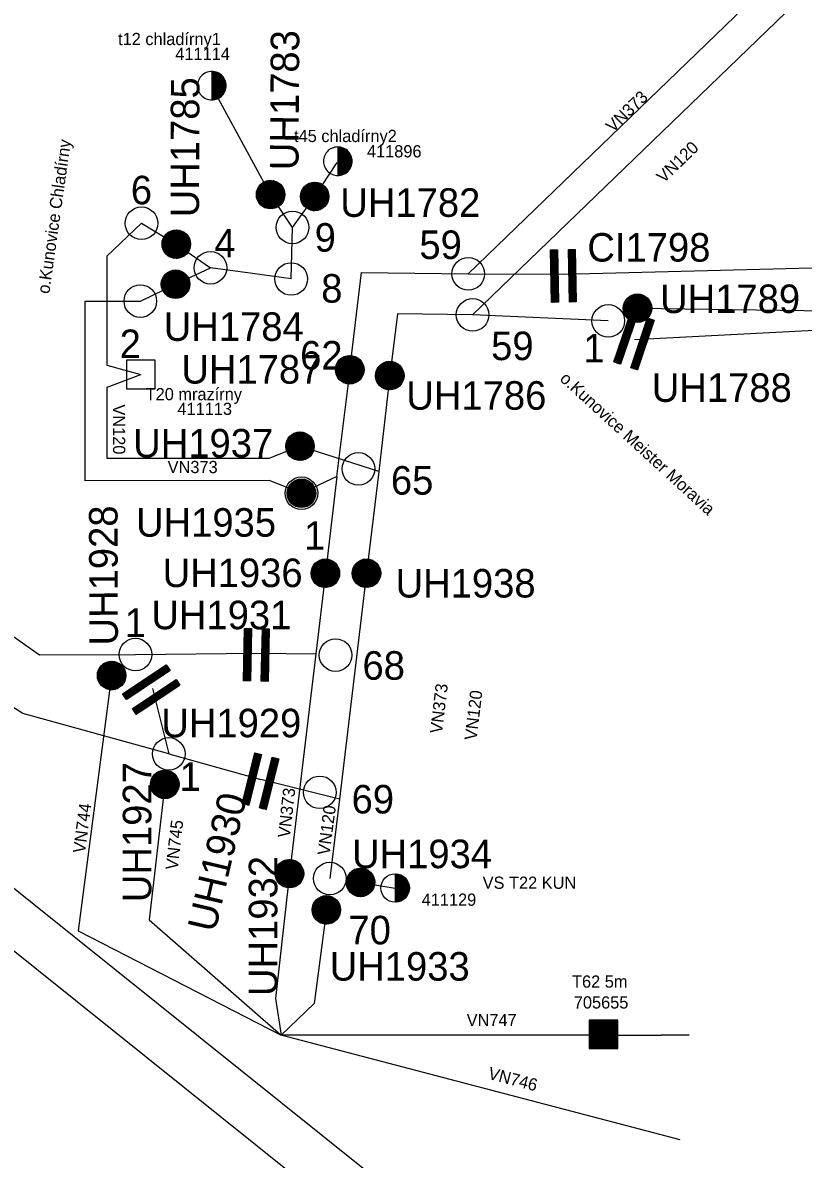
# Model space of a CAD drawing. Extents: x -541654 to -535721, y -1185255 to -1179094.
# Drawn here: x -540417 to -539460, y -1184265 to -1182871 of the extents above; entities that cross this region are included whole.
import ezdxf

# ---------------------------------------------------------------- set-up
doc = ezdxf.new("R2010")
doc.units = 0
for name, color, linetype in [('Default', 7, 'Continuous'), ('Vrstva 1', 7, 'Continuous'), ('Vrstva 2', 7, 'Continuous'), ('Vrstva 20', 7, 'Continuous'), ('Vrstva 3', 7, 'Continuous'), ('Vrstva 5', 7, 'Continuous')]:
    doc.layers.add(name, color=color, linetype=linetype)

# ---------------------------------------------------------------- blocks, each defined once
blk = doc.blocks.new('PS100')
at = {"layer": 'Default'}
for p, q in [((-17.5, -0.7), (0.7, 17.5)), ((-17.5, 0.7), (-0.7, 17.5)), ((-17.4, -2), (2, 17.4)), ((-17.3, 2.2), (-2.2, 17.3)), ((-17.2, -3.3), (3.3, 17.2)), ((-17, 4), (-4, 17)), ((-16.9, -4.4), (4.4, 16.9)), ((-16.6, -5.5), (5.5, 16.6)), ((-16.4, 6), (-6, 16.4)), ((-16.2, -6.5), (6.5, 16.2)), ((-15.8, -7.5), (7.5, 15.8)), ((-15.3, -8.4), (8.4, 15.3)), ((-15.2, 8.6), (-8.6, 15.2)), ((-14.8, -9.3), (9.3, 14.8)), ((-14.2, -10.2), (10.2, 14.2)), ((-13.6, -11), (11, 13.6)), ((-13, -11.7), (11.7, 13)), ((-12.3, -12.5), (12.5, 12.3)), ((-11.5, -13.2), (13.2, 11.5)), ((-10.8, -13.8), (13.8, 10.8)), ((-9.9, -14.4), (14.4, 9.9)), ((-9.1, -14.9), (14.9, 9.1)), ((-8.2, -15.5), (15.5, 8.2)), ((-7.2, -15.9), (15.9, 7.2)), ((-6.2, -16.3), (16.3, 6.2)), ((-5.2, -16.7), (16.7, 5.2)), ((-4.1, -17), (17, 4.1)), ((-2.9, -17.2), (17.2, 2.9)), ((-1.6, -17.4), (17.4, 1.6)), ((-0.3, -17.5), (17.5, 0.3)), ((1.1, -17.4), (17.4, -1.1)), ((2.7, -17.3), (17.3, -2.7)), ((4.5, -16.9), (16.9, -4.5)), ((6.7, -16.2), (16.2, -6.7)), ((9.7, -14.5), (14.5, -9.7))]:
    blk.add_line(p, q, dxfattribs=at)
blk.add_circle((0, 0), 17.5, dxfattribs=at)
blk = doc.blocks.new('PS140')
at = {"layer": 'Default'}
for p, q in [((-17.5, 0), (0, 17.5)), ((-17.4, -1.4), (1.4, 17.4)), ((-17.4, 1.5), (-1.5, 17.4)), ((-17.3, -2.6), (2.6, 17.3)), ((-17.2, 3.1), (-3.1, 17.2)), ((-17.1, -3.8), (3.8, 17.1)), ((-16.8, -4.9), (4.9, 16.8)), ((-16.8, 5), (-5, 16.8)), ((-16.4, -6), (6, 16.4)), ((-16, -7), (7, 16)), ((-15.9, 7.2), (-7.2, 15.9)), ((-15.6, -8), (8, 15.6)), ((-15.1, -8.9), (8.9, 15.1)), ((-14.5, -9.8), (9.8, 14.5)), ((-13.9, -10.6), (10.6, 13.9)), ((-13.8, 10.8), (-10.8, 13.8)), ((-13.3, -11.4), (11.4, 13.3)), ((-12.6, -12.1), (12.1, 12.6)), ((-11.9, -12.8), (12.8, 11.9)), ((-11.2, -13.5), (13.5, 11.2)), ((-10.4, -14.1), (14.1, 10.4)), ((-9.5, -14.7), (14.7, 9.5)), ((-8.6, -15.2), (15.2, 8.6)), ((-7.7, -15.7), (15.7, 7.7)), ((-6.7, -16.1), (16.1, 6.7)), ((-5.7, -16.5), (16.5, 5.7)), ((-4.6, -16.9), (16.9, 4.6)), ((-3.5, -17.1), (17.1, 3.5)), ((-2.3, -17.3), (17.3, 2.3)), ((-1, -17.5), (17.5, 1)), ((0.4, -17.5), (17.5, -0.4)), ((1.9, -17.4), (17.4, -1.9)), ((3.6, -17.1), (17.1, -3.6)), ((5.5, -16.6), (16.6, -5.5)), ((8, -15.6), (15.6, -8))]:
    blk.add_line(p, q, dxfattribs=at)
blk.add_circle((0, 0), 17.5, dxfattribs=at)
blk = doc.blocks.new('PS150')
at = {"layer": 'Default'}
for p, q in [((-15.1, 22.4), (-7.4, 30.1)), ((-15.1, 23.8), (-8.8, 30.1)), ((-15.1, 25.2), (-10.2, 30.1)), ((-15.1, 26.6), (-11.6, 30.1)), ((-15.1, 28), (-13, 30.1)), ((-15.1, 29.4), (-14.4, 30.1)), ((-15.1, 20.9), (-6.5, 29.5)), ((-15.1, 19.5), (-6.5, 28.1)), ((6.7, 22.6), (14.1, 30.1)), ((6.7, 24), (12.7, 30.1)), ((6.7, 25.4), (11.3, 30.1)), ((6.7, 26.8), (9.9, 30.1)), ((6.7, 28.3), (8.5, 30.1)), ((6.7, 29.7), (7, 30.1)), ((6.7, 21.2), (15.2, 29.8)), ((6.7, 19.8), (15.2, 28.3)), ((-15.1, 18.1), (-6.5, 26.7)), ((-15.1, 16.7), (-6.5, 25.3)), ((-15.1, 15.3), (-6.5, 23.9)), ((-15.1, 13.9), (-6.5, 22.4)), ((-15.1, 12.5), (-6.5, 21)), ((-15.1, 11), (-6.5, 19.6)), ((-15.1, 9.6), (-6.5, 18.2)), ((-15.1, 8.2), (-6.5, 16.8)), ((-15.1, 6.8), (-6.5, 15.4)), ((-15.1, 5.4), (-6.5, 14)), ((6.7, 18.4), (15.2, 26.9)), ((6.7, 16.9), (15.2, 25.5)), ((6.7, 15.5), (15.2, 24.1)), ((6.7, 14.1), (15.2, 22.7)), ((6.7, 12.7), (15.2, 21.3)), ((6.7, 11.3), (15.2, 19.9)), ((6.7, 9.9), (15.2, 18.4)), ((6.7, 8.5), (15.2, 17)), ((6.7, 7.1), (15.2, 15.6)), ((6.7, 5.6), (15.2, 14.2)), ((-15.1, 4), (-6.5, 12.5)), ((-15.1, 2.6), (-6.5, 11.1)), ((-15.1, 1.2), (-6.5, 9.7)), ((-15.1, -0.3), (-6.5, 8.3)), ((-15.1, -1.7), (-6.5, 6.9)), ((-15.1, -3.1), (-6.5, 5.5)), ((-15.1, -4.5), (-6.5, 4.1)), ((-15.1, -5.9), (-6.5, 2.6)), ((-15.1, -7.3), (-6.5, 1.2)), ((6.7, 4.2), (15.2, 12.8)), ((6.7, 2.8), (15.2, 11.4)), ((6.7, 1.4), (15.2, 10)), ((6.7, 0), (15.2, 8.5)), ((6.7, -1.4), (15.2, 7.1)), ((6.7, -2.8), (15.2, 5.7)), ((6.7, -4.3), (15.2, 4.3)), ((6.7, -5.7), (15.2, 2.9)), ((6.7, -7.1), (15.2, 1.5)), ((6.7, -8.5), (15.2, 0.1)), ((-15.1, -8.7), (-6.5, -0.2)), ((-15.1, -10.2), (-6.5, -1.6)), ((-15.1, -11.6), (-6.5, -3)), ((-15.1, -13), (-6.5, -4.4)), ((-15.1, -14.4), (-6.5, -5.8)), ((-15.1, -15.8), (-6.5, -7.3)), ((-15.1, -17.2), (-6.5, -8.7)), ((-15.1, -18.6), (-6.5, -10.1)), ((-15.1, -20.1), (-6.5, -11.5)), ((-15.1, -21.5), (-6.5, -12.9)), ((6.7, -9.9), (15.2, -1.4)), ((6.7, -11.3), (15.2, -2.8)), ((6.7, -12.7), (15.2, -4.2)), ((6.7, -14.2), (15.2, -5.6)), ((6.7, -15.6), (15.2, -7)), ((6.7, -17), (15.2, -8.4)), ((6.7, -18.4), (15.2, -9.8)), ((6.7, -19.8), (15.2, -11.3)), ((6.7, -21.2), (15.2, -12.7)), ((-15.1, -22.9), (-6.5, -14.3)), ((-15.1, -24.3), (-6.5, -15.7)), ((-15.1, -25.7), (-6.5, -17.2)), ((-15.1, -27.1), (-6.5, -18.6)), ((-15.1, -28.5), (-6.5, -20)), ((-15.1, -30), (-6.5, -21.4)), ((-15.1, -31.4), (-6.5, -22.8)), ((-15.1, -32.8), (-6.5, -24.2)), ((-15, -34.2), (-6.5, -25.6)), ((-13.6, -34.2), (-6.5, -27.1)), ((6.7, -22.6), (15.2, -14.1)), ((6.7, -24.1), (15.2, -15.5)), ((6.7, -25.5), (15.2, -16.9)), ((6.7, -26.9), (15.2, -18.3)), ((6.7, -28.3), (15.2, -19.7)), ((6.7, -29.7), (15.2, -21.2)), ((6.7, -31.1), (15.2, -22.6)), ((6.7, -32.5), (15.2, -24)), ((6.7, -34), (15.2, -25.4)), ((7.9, -34.2), (15.2, -26.8)), ((-12.2, -34.2), (-6.5, -28.5)), ((-10.8, -34.2), (-6.5, -29.9)), ((-9.4, -34.2), (-6.5, -31.3)), ((-8, -34.2), (-6.5, -32.7)), ((-6.5, -34.2), (-6.5, -34.1)), ((9.3, -34.2), (15.2, -28.2)), ((10.7, -34.2), (15.2, -29.6)), ((12.1, -34.2), (15.2, -31)), ((13.5, -34.2), (15.2, -32.5)), ((14.9, -34.2), (15.2, -33.9))]:
    blk.add_line(p, q, dxfattribs=at)
for points in [[(-6.5, 30.1), (-6.5, -34.2), (-15.1, -34.2), (-15.1, 30.1)], [(15.2, 30.1), (15.2, -34.2), (6.7, -34.2), (6.7, 30.1)]]:
    blk.add_lwpolyline(points, close=True, dxfattribs=at)
blk = doc.blocks.new('PS610')
at = {"layer": 'Default'}
for p, q in [((0, 16.2), (1.3, 17.4)), ((0, 14.7), (2.5, 17.3)), ((0, 13.3), (3.7, 17.1)), ((0, 11.9), (4.9, 16.8)), ((0, 10.5), (5.9, 16.4)), ((0, 9.1), (7, 16)), ((0, 7.7), (7.9, 15.6)), ((0, 6.3), (8.8, 15.1)), ((0, 4.8), (9.7, 14.5)), ((0, 3.4), (10.5, 14)), ((0, 2), (11.3, 13.3)), ((0, 0.6), (12, 12.7)), ((0, -0.8), (12.8, 12)), ((0, -2.2), (13.4, 11.2)), ((0, -3.6), (14, 10.4)), ((0, -5), (14.6, 9.6)), ((0, -6.5), (15.2, 8.7)), ((0, -7.9), (15.6, 7.8)), ((0, -9.3), (16.1, 6.8)), ((0, -10.7), (16.5, 5.8)), ((0, -12.1), (16.8, 4.7)), ((0, -13.5), (17.1, 3.6)), ((0, -14.9), (17.3, 2.4)), ((0, -16.4), (17.4, 1.1)), ((0.3, -17.5), (17.5, -0.3)), ((1.8, -17.4), (17.4, -1.8)), ((3.5, -17.1), (17.1, -3.5)), ((5.4, -16.7), (16.7, -5.4)), ((7.8, -15.7), (15.6, -7.8))]:
    blk.add_line(p, q, dxfattribs=at)
blk.add_lwpolyline([(0, 17.5), (0, -17.5)], dxfattribs=at)
blk.add_circle((0, 0), 17.5, dxfattribs=at)
blk = doc.blocks.new('PS800')
at = {"layer": 'Vrstva 2'}
blk.add_circle((0, 0), 20, dxfattribs=at)
blk = doc.blocks.new('PS650')
at = {"layer": 'Vrstva 20'}
for points in [[(17.5, 17.5), (-17.5, 17.5)], [(-17.5, 17.5), (-17.5, -17.5)], [(17.5, -17.5), (17.5, 17.5)], [(-17.5, -17.5), (17.5, -17.5)]]:
    blk.add_lwpolyline(points, dxfattribs=at)
blk = doc.blocks.new('PS630')
at = {"layer": 'Default'}
for p, q in [((-16.6, -14.9), (17.1, 18.7)), ((-16.6, -13.5), (15.7, 18.7)), ((-16.6, -12.1), (14.2, 18.7)), ((-16.6, -10.7), (12.8, 18.7)), ((-16.6, -9.3), (11.4, 18.7)), ((-16.6, -7.9), (10, 18.7)), ((-16.6, -6.5), (8.6, 18.7)), ((-16.6, -5), (7.2, 18.7)), ((-16.6, -3.6), (5.8, 18.7)), ((-16.6, -2.2), (4.3, 18.7)), ((-16.6, -0.8), (2.9, 18.7)), ((-16.6, 0.6), (1.5, 18.7)), ((-16.6, 2), (0.1, 18.7)), ((-16.6, 3.4), (-1.3, 18.7)), ((-16.6, 4.9), (-2.7, 18.7)), ((-16.6, 6.3), (-4.1, 18.7)), ((-16.6, 7.7), (-5.6, 18.7)), ((-16.6, 9.1), (-7, 18.7)), ((-16.6, 10.5), (-8.4, 18.7)), ((-16.6, 11.9), (-9.8, 18.7)), ((-16.6, 13.3), (-11.2, 18.7)), ((-16.6, 14.8), (-12.6, 18.7)), ((-16.6, 16.2), (-14, 18.7)), ((-16.6, 17.6), (-15.5, 18.7)), ((-16.5, -16.3), (18.4, 18.6)), ((-15.1, -16.3), (18.4, 17.2)), ((-13.7, -16.3), (18.4, 15.8)), ((-12.3, -16.3), (18.4, 14.4)), ((-10.9, -16.3), (18.4, 13)), ((-9.4, -16.3), (18.4, 11.6)), ((-8, -16.3), (18.4, 10.2)), ((-6.6, -16.3), (18.4, 8.7)), ((-5.2, -16.3), (18.4, 7.3)), ((-3.8, -16.3), (18.4, 5.9)), ((-2.4, -16.3), (18.4, 4.5)), ((-1, -16.3), (18.4, 3.1)), ((0.5, -16.3), (18.4, 1.7)), ((1.9, -16.3), (18.4, 0.3)), ((3.3, -16.3), (18.4, -1.2)), ((4.7, -16.3), (18.4, -2.6)), ((6.1, -16.3), (18.4, -4)), ((7.5, -16.3), (18.4, -5.4)), ((8.9, -16.3), (18.4, -6.8)), ((10.4, -16.3), (18.4, -8.2)), ((11.8, -16.3), (18.4, -9.6)), ((13.2, -16.3), (18.4, -11.1)), ((14.6, -16.3), (18.4, -12.5)), ((16, -16.3), (18.4, -13.9)), ((17.4, -16.3), (18.4, -15.3))]:
    blk.add_line(p, q, dxfattribs=at)
for points in [[(-16.6, 18.7), (-16.6, -16.3)], [(18.4, 18.7), (-16.6, 18.7)], [(-16.6, 18.7), (-16.6, -16.3)], [(18.4, -16.3), (18.4, 18.7)], [(-16.6, -16.3), (18.4, -16.3)]]:
    blk.add_lwpolyline(points, dxfattribs=at)
blk = doc.blocks.new('PS611')
at = {"layer": 'Default'}
for p, q in [((0, 16.2), (1.3, 17.4)), ((0, 14.7), (2.5, 17.3)), ((0, 13.3), (3.7, 17.1)), ((0, 11.9), (4.9, 16.8)), ((0, 10.5), (5.9, 16.4)), ((0, 9.1), (7, 16)), ((0, 7.7), (7.9, 15.6)), ((0, 6.3), (8.8, 15.1)), ((0, 4.8), (9.7, 14.5)), ((0, 3.4), (10.5, 14)), ((0, 2), (11.3, 13.3)), ((0, 0.6), (12, 12.7)), ((0, -0.8), (12.8, 12)), ((0, -2.2), (13.4, 11.2)), ((0, -3.6), (14, 10.4)), ((0, -5), (14.6, 9.6)), ((0, -6.5), (15.2, 8.7)), ((0, -7.9), (15.6, 7.8)), ((0, -9.3), (16.1, 6.8)), ((0, -10.7), (16.5, 5.8)), ((0, -12.1), (16.8, 4.7)), ((0, -13.5), (17.1, 3.6)), ((0, -14.9), (17.3, 2.4)), ((0, -16.4), (17.4, 1.1)), ((0.3, -17.5), (17.5, -0.3)), ((1.8, -17.4), (17.4, -1.8)), ((3.5, -17.1), (17.1, -3.5)), ((5.4, -16.7), (16.7, -5.4)), ((7.8, -15.7), (15.6, -7.8))]:
    blk.add_line(p, q, dxfattribs=at)
for points in [[(17.5, 0), (17.4, 1.8), (17.1, 3.6), (16.6, 5.4), (16, 7.1), (15.2, 8.8), (14.2, 10.3), (13, 11.7), (11.7, 13), (10.3, 14.2), (8.7, 15.2), (7.1, 16), (5.4, 16.6), (3.6, 17.1), (1.8, 17.4), (0, 17.5), (-1.8, 17.4), (-3.6, 17.1), (-5.4, 16.6), (-7.1, 16), (-8.8, 15.2), (-10.3, 14.2), (-11.7, 13), (-13, 11.7), (-14.2, 10.3), (-15.2, 8.7), (-16, 7.1), (-16.6, 5.4), (-17.1, 3.6), (-17.4, 1.8), (-17.5, 0), (-17.4, -1.8), (-17.1, -3.6), (-16.6, -5.4), (-16, -7.1), (-15.2, -8.8), (-14.2, -10.3), (-13, -11.7), (-11.7, -13), (-10.3, -14.2), (-8.8, -15.2), (-7.1, -16), (-5.4, -16.6), (-3.6, -17.1), (-1.8, -17.4), (0, -17.5), (1.8, -17.4), (3.6, -17.1), (5.4, -16.6), (7.1, -16), (8.8, -15.2), (10.3, -14.2), (11.7, -13), (13, -11.7), (14.2, -10.3), (15.2, -8.8), (16, -7.1), (16.6, -5.4), (17.1, -3.6), (17.4, -1.8), (17.5, 0)], [(0, 17.5), (0, -17.5)]]:
    blk.add_lwpolyline(points, dxfattribs=at)

msp = doc.modelspace()

# ---------------------------------------------------------------- linework, layer by layer
at = {"layer": 'Default'}
for points in [[(-535721.4, -1181322.7), (-538502.4, -1179093.8), (-541654.5, -1183026.4), (-538873.5, -1185255.4)], [(-535805.8, -1181332), (-538493.1, -1179178.1), (-541570.1, -1183017.1), (-538882.8, -1185171.1)]]:
    msp.add_lwpolyline(points, close=True, dxfattribs=at)
at = {"layer": 'Vrstva 1'}
for points in [[(-538730.2, -1181781.1), (-538745.8, -1181888.8), (-538896.2, -1182293.4), (-539271.4, -1182655.8), (-539865.4, -1183229.4)], [(-539870.7, -1183179.1), (-539298.4, -1182626.3)], [(-540113.1, -1183082), (-540184.9, -1182950.2)], [(-540059.1, -1183084.2), (-540031.4, -1183042.7)], [(-540086.3, -1183122.1), (-540113.1, -1183082)], [(-540086.3, -1183122.1), (-540059.1, -1183084.2)], [(-540313.8, -1183157.6), (-540271.5, -1183117.1)], [(-540271.5, -1183117.1), (-540228.8, -1183142.7)], [(-540087.9, -1183185.4), (-540086.3, -1183122.1)], [(-540228.8, -1183142.7), (-540186.9, -1183171.6)], [(-540313.8, -1183157.6), (-540313.8, -1183291.1), (-540272.4, -1183302.6)], [(-540229.7, -1183191.8), (-540186.9, -1183171.6)], [(-540135.2, -1183178.8), (-540186.9, -1183171.6)], [(-539754.1, -1183179.6), (-539433, -1183171.4), (-539338.5, -1183192.6)], [(-540087.9, -1183185.4), (-540135.2, -1183178.8)], [(-540016.1, -1183296.7), (-540001.7, -1183177.6), (-539870.7, -1183179.1)], [(-539870.7, -1183179.1), (-539754.1, -1183179.6)], [(-540272.9, -1183212.5), (-540229.7, -1183191.8)], [(-540075.3, -1183448.2), (-540115.1, -1183432.6), (-540340.7, -1183432.8), (-540340.6, -1183212.5), (-540272.9, -1183212.5)], [(-539865.4, -1183229.4), (-539957.4, -1183228.3), (-539967, -1183303.9)], [(-539699, -1183236.8), (-539865.4, -1183229.4), (-539865.4, -1183229.4)], [(-539663.2, -1183221.2), (-539429.6, -1183224.5), (-539429.6, -1183393.8), (-539292.9, -1183393.8)], [(-539666.8, -1183259.6), (-539335.9, -1183242.5)], [(-540016.1, -1183296.7), (-540032.2, -1183427.6)], [(-540077.1, -1183390.5), (-540115.2, -1183405.7), (-540313.4, -1183405.6), (-540313.4, -1183318), (-540272.4, -1183302.6)], [(-539967, -1183303.9), (-539980.5, -1183421.3)], [(-539980.5, -1183421.3), (-540077.1, -1183390.5)], [(-539980.5, -1183421.3), (-539995.6, -1183546.3)], [(-540032.1, -1183427.6), (-540075.3, -1183448.2)], [(-540032.1, -1183427.6), (-540046, -1183546.3)], [(-540046, -1183546.3), (-540057.8, -1183644.9)], [(-539995.6, -1183546.3), (-540028.8, -1183823.3)], [(-540238, -1183767.8), (-540417.2, -1183718.4), (-540591.8, -1183607), (-541124.4, -1183583.7)], [(-540470.7, -1183594.2), (-540396.7, -1183646.3), (-540278.9, -1183646)], [(-540278.9, -1183646), (-540130.6, -1183644.3)], [(-540130.6, -1183644.3), (-540057.8, -1183644.9)], [(-540057.8, -1183644.9), (-540090, -1183914.6)], [(-540308.1, -1183671.6), (-540349.2, -1183984.9), (-540100, -1184112.8)], [(-540257.8, -1183687.7), (-540238, -1183767.8)], [(-540238, -1183767.8), (-540125.1, -1183799.2)], [(-540028.8, -1183823.3), (-540125.1, -1183799.2)], [(-540242.9, -1183805.1), (-540262.2, -1183971.2), (-540100, -1184112.8)], [(-540028.8, -1183823.3), (-540040.5, -1183920.6)], [(-540090, -1183914.6), (-540107, -1184067.6), (-540100, -1184112.8)], [(-540002.9, -1183925.4), (-539960.4, -1183932.2)], [(-540044.8, -1183959), (-540059.8, -1184073.9), (-540100, -1184112.8)], [(-539610.8, -1184241), (-540100, -1184112.8)], [(-539724.5, -1184112.8), (-540100, -1184112.8)], [(-539705.8, -1184112.8), (-539724.5, -1184112.8)], [(-539705.8, -1184112.8), (-539634.1, -1184112.6)], [(-539600, -1184112.8), (-539634.1, -1184112.6)]]:
    msp.add_lwpolyline(points, dxfattribs=at)

# ---------------------------------------------------------------- block references
at = {"layer": 'Vrstva 2'}
for name, p, rotation in [('PS140', (-540113.1, -1183082), 107.19590279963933), ('PS140', (-540059.1, -1183084.2), -66.5734055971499), ('PS140', (-540228.8, -1183142.7), -28.299599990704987), ('PS150', (-539754.1, -1183179.6), 1.0974722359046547), ('PS140', (-540229.7, -1183191.8), -137.72051106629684), ('PS140', (-539663.2, -1183221.2), 43.89927496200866), ('PS150', (-539666.8, -1183259.6), -18.630803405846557), ('PS140', (-540016.1, -1183296.7), 84.6160527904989), ('PS140', (-539967, -1183303.9), 81.48321110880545), ('PS140', (-540077.1, -1183390.5), 7.688058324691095), ('PS140', (-540075.3, -1183448.2), 59.104705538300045), ('PS140', (-540046, -1183546.3), 82.97227774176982), ('PS140', (-539995.6, -1183546.3), -96.68660837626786), ('PS150', (-540130.6, -1183644.3), -1.1817719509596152), ('PS140', (-540308.1, -1183671.6), -5.999733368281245), ('PS150', (-540257.8, -1183687.7), -56.342046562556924), ('PS150', (-540125.1, -1183799.2), -13.995237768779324), ('PS100', (-540242.9, -1183805.1), -153.43188052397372), ('PS140', (-540090, -1183914.6), 70.46426947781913), ('PS140', (-540002.9, -1183925.4), -94.40686662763), ('PS140', (-540044.8, -1183959), -61.5249416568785)]:
    msp.add_blockref(name, p, dxfattribs=dict(at, rotation=rotation))
at = {"layer": 'Vrstva 3'}
for name, p in [('PS611', (-540185.2, -1182948.3)), ('PS611', (-540030.7, -1183041)), ('PS650', (-540272.4, -1183302.6)), ('PS610', (-539960.4, -1183932.2)), ('PS630', (-539705.8, -1184112.8))]:
    msp.add_blockref(name, p, dxfattribs=at)
at = {"layer": 'Vrstva 5'}
for p, rotation in [((-540271.5, -1183117.1), 81.87711381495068), ((-540086.3, -1183122.1), -14.150816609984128), ((-540186.9, -1183171.6), 79.52871106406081), ((-539870.7, -1183179.1), 5.629222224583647), ((-540087.9, -1183185.4), -10.367486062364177), ((-540272.9, -1183212.5), -78.54001944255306), ((-539865.4, -1183229.4), 5.814858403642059), ((-539699, -1183236.8), 5.99906389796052), ((-540005.5, -1183418.3), 84.0429694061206), ((-540075.3, -1183448.2), -70.16778056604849), ((-540075.3, -1183448.2), -93.51351665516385), ((-540278.9, -1183646), -7.290502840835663), ((-540033.5, -1183646.6), -9.78719996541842), ((-540238, -1183767.8), -24.336652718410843), ((-540052.9, -1183814.9), -19.91056951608)]:
    msp.add_blockref('PS800', p, dxfattribs=dict(at, rotation=rotation))
msp.add_blockref('PS800', (-540040.5, -1183920.6), dxfattribs=at)

# ---------------------------------------------------------------- texts
at = {"layer": 'Vrstva 1'}
for s, rotation, p in [('VN373', 44.008, (-539693.3, -1183006.6)), ('o.Kunovice Chladírny', 81.938, (-540384.6, -1183204.2)), ('VN120', 44, (-539631.1, -1183068.6)), ('o.Kunovice Meister Moravia', 317.59, (-539759.5, -1183309.2)), ('VN120', 270.233, (-540306.6, -1183339.2)), ('VN373', 0.039, (-540239.4, -1183423.5)), ('VN373', 83.207, (-539902.9, -1183743.4)), ('VN120', 83.174, (-539860.6, -1183751.6)), ('VN373', 83.635, (-540089.5, -1183871.2)), ('VN744', 82.523, (-540340.8, -1183890.2)), ('VN120', 82.563, (-540040.9, -1183892.7)), ('VN745', 83.382, (-540227.2, -1183910.6)), ('VN746', 345.317, (-539847.5, -1184166))]:
    msp.add_text(s, height=15, rotation=rotation, dxfattribs=at).set_placement(p)
msp.add_text('VN747', height=15, dxfattribs=at).set_placement((-539872.7, -1184101.6))
at = {"layer": 'Vrstva 2'}
for s, rotation, p in [('UH1783', 89.628, (-540079, -1183052.1)), ('UH1785', 89.849, (-540200.9, -1183109.8)), ('UH1928', 90.175, (-540300.4, -1183634.8)), ('UH1927', 90, (-540259.4, -1183949.6)), ('UH1930', 76.851, (-540181.2, -1183987.8)), ('UH1932', 90, (-540104.9, -1184064.7))]:
    msp.add_text(s, height=35, rotation=rotation, dxfattribs=at).set_placement(p)
for s, p in [('UH1782', (-540027.7, -1183109.2)), ('CI1798', (-539724.7, -1183164.1)), ('UH1789', (-539635.5, -1183227.2)), ('UH1784', (-540244.2, -1183261.3)), ('UH1787', (-540222.6, -1183313.7)), ('UH1786', (-539946.7, -1183345.7)), ('UH1788', (-539645.7, -1183336.1)), ('UH1937', (-540281.7, -1183404.3)), ('UH1935', (-540278.2, -1183501.4)), ('UH1936', (-540245.6, -1183563.2)), ('UH1938', (-539959.9, -1183576)), ('UH1931', (-540259.4, -1183614.9)), ('UH1929', (-540247.2, -1183747.4)), ('UH1934', (-540013.3, -1183907.9)), ('UH1933', (-540040.7, -1184045.8))]:
    msp.add_text(s, height=35, dxfattribs=at).set_placement(p)
at = {"layer": 'Vrstva 3'}
for s, p in [('t12 chladírny1', (-540300.2, -1182898.6)), ('411114', (-540230, -1182916.8)), ('t45 chladírny2', (-540084.4, -1183017.5)), ('411896', (-539995, -1183036.3)), ('T20 mrazírny', (-540266.4, -1183334.1)), ('411113', (-540227.4, -1183352.1)), ('VS T22 KUN', (-539853.1, -1183933.2)), ('411129', (-539927.9, -1183954)), ('T62 5m', (-539743.5, -1184054.4)), ('705655', (-539741.3, -1184080))]:
    msp.add_text(s, height=15, dxfattribs=at).set_placement(p)
at = {"layer": 'Vrstva 5'}
for s, p in [('6', (-540284.6, -1183093.8)), ('9', (-540059.1, -1183151.9)), ('4', (-540182.2, -1183159)), ('59', (-539930.7, -1183160.9)), ('8', (-540051.1, -1183214.4)), ('2', (-540298.3, -1183282.4)), ('59', (-539842.7, -1183284.9)), ('1', (-539729.7, -1183287.8)), ('62', (-540077, -1183296.4)), ('65', (-539965.6, -1183449.8)), ('1', (-540072.1, -1183517.5)), ('1', (-540292.1, -1183624.4)), ('68', (-540000.5, -1183676.8)), ('1', (-540224.8, -1183813.1)), ('69', (-540013.8, -1183840.8)), ('70', (-540017.7, -1184001.3))]:
    msp.add_text(s, height=35, dxfattribs=at).set_placement(p)

doc.saveas('drawing.dxf')
